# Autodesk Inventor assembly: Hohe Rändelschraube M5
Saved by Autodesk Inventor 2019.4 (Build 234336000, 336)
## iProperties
Created: 2021-06
Part Number: Hohe Rändelschraube M5
Document SubType Name: Assembly
Designer: Administrator
Title: Hohe Rändelschraube M5 v2
Author: Administrator
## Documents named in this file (2)
- c:\worker\convert-fusion-r04\tmp\job-1\39\output\files\e1e84fd7-b652-4e3d-a1c7-f0a54bbc30a7\Hohe Rändelschraube M5 v2_1.iam
- c:\worker\convert-fusion-r04\tmp\job-1\39\output\files\e1e84fd7-b652-4e3d-a1c7-f0a54bbc30a7\_Knurled screw DIN 464-M5-12-ZB.ipt
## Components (1 placed, 1 different names)
1. _Knurled screw DIN 464-M5-12-ZB:1
